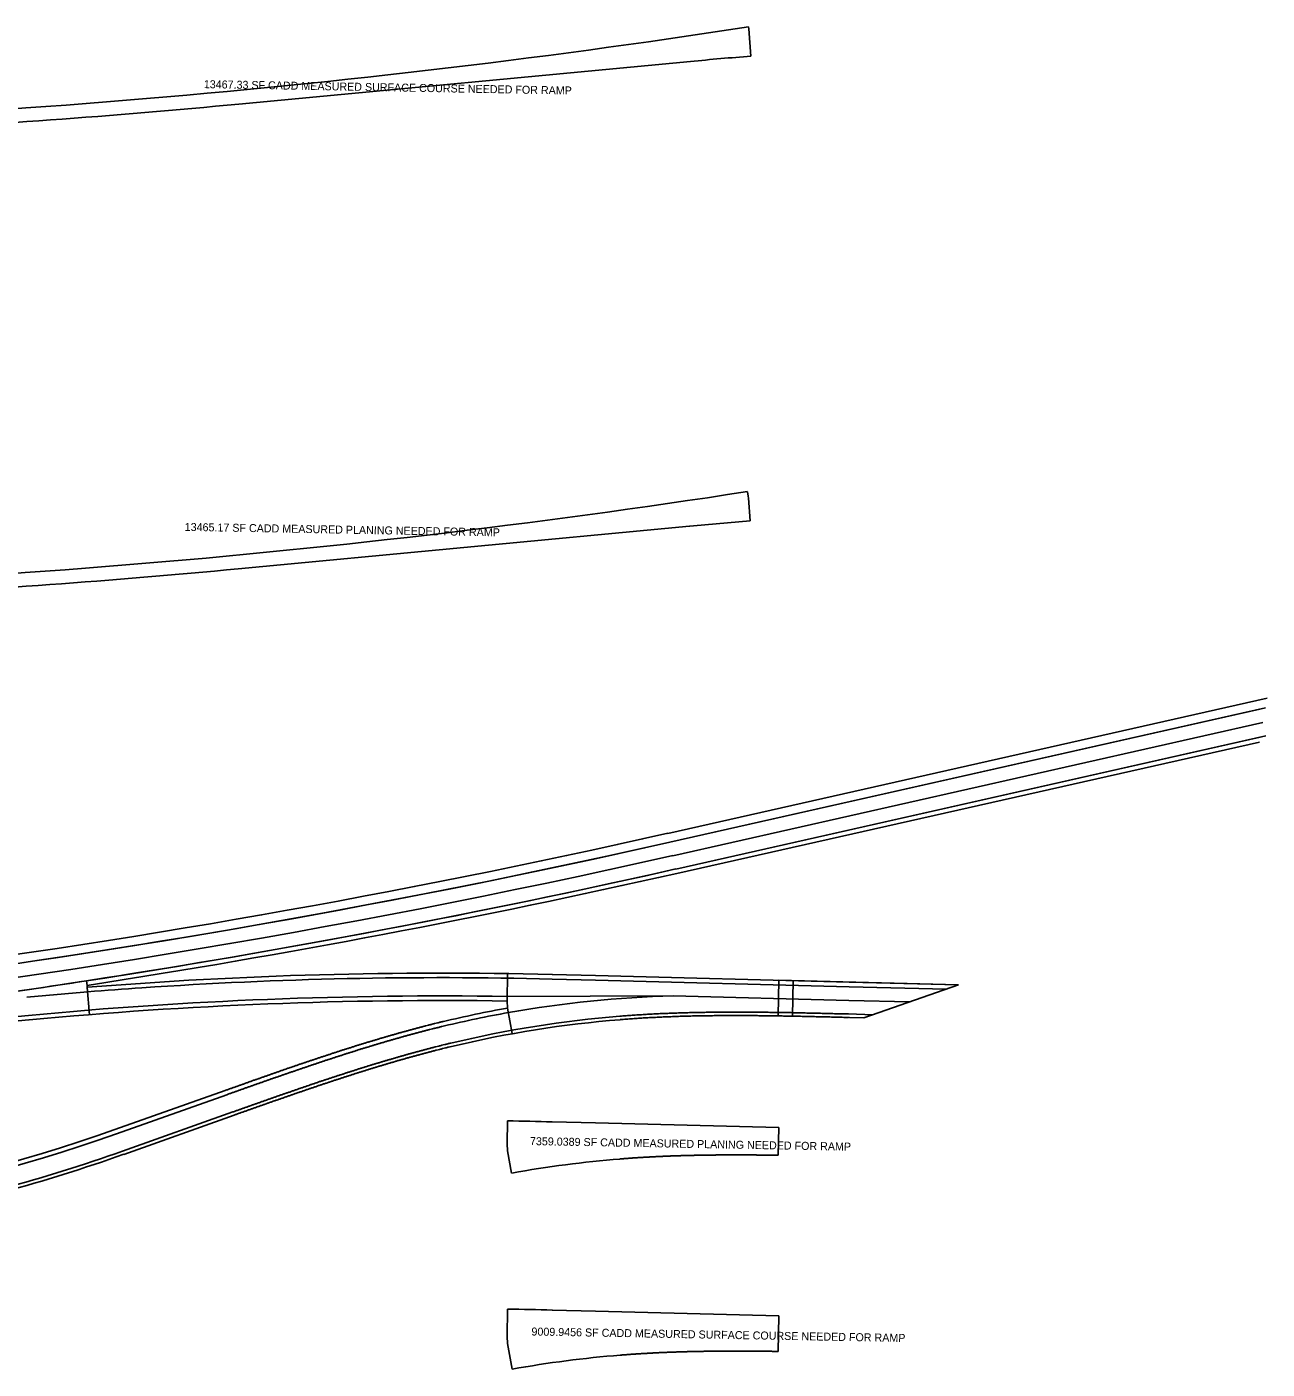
# Model space of a CAD drawing. Extents: x 8527 to 36635, y 12099 to 39012.
# Drawn here: x 10781 to 11866, y 33269 to 34444 of the extents above; entities that cross this region are included whole.
import ezdxf

# ---------------------------------------------------------------- set-up
doc = ezdxf.new("R2010")
doc.units = 0
for name, color, linetype in [('DR_P_Inlet_Protection', 7, 'Continuous'), ('MT_P_Dotted_Line', 7, 'Continuous'), ('MT_P_Traffic_Attenuator', 7, 'Continuous'), ('PV_X_EOP', 7, 'Continuous'), ('SH_Text', 7, 'Continuous')]:
    doc.layers.add(name, color=color, linetype=linetype)

msp = doc.modelspace()

# ---------------------------------------------------------------- linework, layer by layer
at = {"layer": 'DR_P_Inlet_Protection'}
msp.add_line((11345.8, 33718.3), (11861.9, 33834.8), dxfattribs=at)
msp.add_arc((9664.2, 41170.4), 7639.4, 269.175, 282.71667, dxfattribs=at)
at = {"layer": 'MT_P_Dotted_Line'}
for p, q in [((11201, 33595.2), (11346.1, 33595.7)), ((11346.1, 33595.7), (11499.8, 33591.7)), ((11499.8, 33591.7), (11553, 33590.4))]:
    msp.add_line(p, q, dxfattribs=at)
msp.add_arc((11369.8, 32641), 954.9, 91.4213, 100.1187, dxfattribs=at)
at = {"layer": 'MT_P_Traffic_Attenuator'}
for p, q in [((11341.4, 33737.8), (11865.7, 33856.1)), ((11349.4, 33702.7), (11858.9, 33817.7)), ((11201.3, 33615.2), (11200.9, 33591.2)), ((11240.4, 33614.4), (11278.2, 33613.4)), ((11278.2, 33613.4), (11500.2, 33607.7)), ((10833.5, 33604.8), (10833.6, 33603.1)), ((11500.2, 33607.7), (11595.8, 33605.3)), ((11205.3, 33562.6), (11201.3, 33585)), ((10387.7, 33537.1), (10782.6, 33574.6)), ((10857.8, 33478.7), (10954.3, 33512.9)), ((10865.5, 33457), (10962, 33491.2))]:
    msp.add_line(p, q, dxfattribs=at)
for centre, radius, start, end in [((9664.2, 41170.4), 7619.4, 271.81542, 282.71667), ((9664.2, 41170.4), 7655.4, 278.78578, 282.71667), ((11142.7, 29775.9), 3839.7, 88.5417, 94.6175), ((11142.7, 29775.9), 3815.7, 89.126, 95.4147), ((11369.8, 32641), 958.9, 100.1187, 103.5417), ((11375.2, 32625.9), 951.9, 94.5417, 103.5417), ((10380, 34824.8), 1428.4, 268.0856, 289.5417), ((10380, 34824.8), 1451.4, 280.8886, 289.5417)]:
    msp.add_arc(centre, radius, start, end, dxfattribs=at)
for points in [[(11299.8, 33574.9), (11302.5, 33575.1), (11305.2, 33575.3), (11307.9, 33575.5), (11310.5, 33575.7), (11313.2, 33575.9), (11315.9, 33576), (11318.6, 33576.2), (11321.3, 33576.4), (11324, 33576.5), (11326.7, 33576.7), (11329.4, 33576.8), (11332.1, 33576.9), (11334.8, 33577.1), (11337.5, 33577.2), (11340.1, 33577.3), (11342.8, 33577.4), (11345.5, 33577.5), (11348.2, 33577.6), (11350.9, 33577.7), (11353.6, 33577.8), (11356.3, 33577.8), (11359, 33577.9), (11361.7, 33578), (11364.4, 33578.1), (11367.1, 33578.1), (11369.8, 33578.2), (11372.5, 33578.2), (11375.2, 33578.3), (11377.9, 33578.3), (11380.6, 33578.3), (11383.3, 33578.4), (11386, 33578.4), (11388.7, 33578.4), (11391.4, 33578.4), (11394.1, 33578.4), (11396.8, 33578.4), (11399.5, 33578.4), (11402.2, 33578.4), (11404.9, 33578.4), (11407.6, 33578.4), (11410.3, 33578.4), (11413, 33578.4), (11415.7, 33578.4), (11418.4, 33578.4), (11421.1, 33578.3), (11423.8, 33578.3), (11426.5, 33578.3), (11429.2, 33578.3), (11431.9, 33578.2), (11434.6, 33578.2), (11437.3, 33578.1), (11440, 33578.1), (11442.7, 33578), (11445.4, 33578), (11448.1, 33578), (11450.8, 33577.9), (11453.5, 33577.8), (11456.2, 33577.8), (11458.9, 33577.7), (11461.6, 33577.7), (11464.3, 33577.6), (11467, 33577.6), (11469.7, 33577.5), (11472.4, 33577.4), (11475.1, 33577.4), (11477.8, 33577.3), (11480.5, 33577.2), (11483.2, 33577.2), (11485.9, 33577.1), (11488.6, 33577), (11491.3, 33577), (11494, 33576.9), (11496.7, 33576.8), (11499.4, 33576.8)], [(10954.3, 33512.9), (10956.8, 33513.8), (10959.4, 33514.7), (10961.9, 33515.6), (10964.5, 33516.5), (10967, 33517.4), (10969.6, 33518.3), (10972.1, 33519.2), (10974.7, 33520.1), (10977.2, 33521.1), (10979.8, 33522), (10982.3, 33522.8), (10984.9, 33523.7), (10987.4, 33524.6), (10990, 33525.5), (10992.5, 33526.4), (10995.1, 33527.3), (10997.6, 33528.2), (11000.2, 33529.1), (11002.7, 33530), (11005.3, 33530.9), (11007.8, 33531.8), (11010.4, 33532.7), (11013, 33533.5), (11015.5, 33534.4), (11018.1, 33535.3), (11020.6, 33536.2), (11023.2, 33537), (11025.8, 33537.9), (11028.3, 33538.8), (11030.9, 33539.6), (11033.5, 33540.5), (11036, 33541.3), (11038.6, 33542.2), (11041.2, 33543), (11043.8, 33543.9), (11046.3, 33544.7), (11048.9, 33545.6), (11051.5, 33546.4), (11054.1, 33547.3), (11056.6, 33548.1), (11059.2, 33548.9), (11061.8, 33549.7), (11064.4, 33550.5), (11067, 33551.4), (11069.5, 33552.2), (11072.1, 33553), (11074.7, 33553.8), (11077.3, 33554.6), (11079.9, 33555.4), (11082.5, 33556.1), (11085.1, 33556.9), (11087.7, 33557.7), (11090.3, 33558.5), (11092.9, 33559.2), (11095.5, 33560), (11098.1, 33560.8), (11100.7, 33561.5), (11103.3, 33562.2), (11105.9, 33563), (11108.5, 33563.7), (11111.1, 33564.4), (11113.8, 33565.2), (11116.4, 33565.9), (11119, 33566.6), (11121.6, 33567.3), (11124.2, 33568), (11126.9, 33568.7), (11129.5, 33569.4), (11132.1, 33570), (11134.7, 33570.7), (11137.4, 33571.4), (11140, 33572), (11142.6, 33572.7), (11145.3, 33573.3)], [(10962, 33491.2), (10964.5, 33492.2), (10967.1, 33493.1), (10969.6, 33494), (10972.2, 33494.9), (10974.7, 33495.8), (10977.2, 33496.7), (10979.8, 33497.6), (10982.3, 33498.5), (10984.9, 33499.4), (10987.4, 33500.3), (10990, 33501.2), (10992.5, 33502.1), (10995.1, 33503), (10997.6, 33503.9), (11000.2, 33504.7), (11002.7, 33505.6), (11005.3, 33506.5), (11007.8, 33507.4), (11010.4, 33508.3), (11012.9, 33509.2), (11015.5, 33510.1), (11018, 33511), (11020.6, 33511.8), (11023.1, 33512.7), (11025.7, 33513.6), (11028.3, 33514.5), (11030.8, 33515.3), (11033.4, 33516.2), (11035.9, 33517.1), (11038.5, 33517.9), (11041, 33518.8), (11043.6, 33519.6), (11046.2, 33520.5), (11048.7, 33521.3), (11051.3, 33522.2), (11053.9, 33523), (11056.4, 33523.8), (11059, 33524.7), (11061.6, 33525.5), (11064.1, 33526.3), (11066.7, 33527.2), (11069.3, 33528), (11071.8, 33528.8), (11074.4, 33529.6), (11077, 33530.4), (11079.6, 33531.2), (11082.1, 33532), (11084.7, 33532.8), (11087.3, 33533.6), (11089.9, 33534.4), (11092.5, 33535.1), (11095, 33535.9), (11097.6, 33536.7), (11100.2, 33537.4), (11102.8, 33538.2), (11105.4, 33539), (11108, 33539.7), (11110.6, 33540.4), (11113.2, 33541.2), (11115.8, 33541.9), (11118.4, 33542.6), (11121, 33543.3), (11123.6, 33544), (11126.2, 33544.7), (11128.8, 33545.4), (11131.4, 33546.1), (11134, 33546.8), (11136.6, 33547.5), (11139.2, 33548.2), (11141.8, 33548.8), (11144.4, 33549.5), (11147, 33550.1), (11149.7, 33550.8), (11152.3, 33551.4)]]:
    msp.add_spline(points, degree=3, dxfattribs=at)
at = {"layer": 'PV_X_EOP'}
msp.add_arc((11142.7, 29775.9), 3835.7, 94.6175, 95.4147, dxfattribs=at)
at = {"layer": 'SH_Text'}
for p, q in [((11412, 34443.5), (11412.2, 34441.9)), ((11412.2, 34441.9), (11414.1, 34418)), ((11361.2, 34413.3), (10966.3, 34375.9)), ((11411.1, 34036.8), (11411.7, 34032.9)), ((11411.7, 34032.9), (11411.9, 34031.2)), ((11411.9, 34031.2), (11413.5, 34011.3)), ((11360.5, 34006.7), (10965.6, 33969.2)), ((11343.2, 33730), (11864.2, 33847.6)), ((11343.2, 33730), (11859.3, 33846.5)), ((11348.5, 33706.6), (11864.6, 33823.1)), ((11348.5, 33706.6), (11859.7, 33822)), ((10832.8, 33608.7), (10833.5, 33604.8)), ((10835.5, 33579.2), (10833.6, 33603.1)), ((11240.3, 33610.4), (11278.1, 33609.4)), ((11278.1, 33609.4), (11500.1, 33603.7)), ((11438, 33578.1), (11438.5, 33609.3)), ((11438.5, 33609.3), (11438, 33578.1)), ((11438.5, 33609.3), (11595.8, 33605.3)), ((11451, 33609.1), (11450.5, 33577.9)), ((11500.1, 33603.7), (11585.1, 33601.6)), ((11595.8, 33605.3), (11512.9, 33576.4)), ((11201.3, 33585), (11200.9, 33591.2)), ((10387.3, 33541.1), (10782.3, 33578.6)), ((11512.9, 33576.4), (11438, 33578.1)), ((11499.4, 33579.8), (11499.5, 33579.8)), ((11499.5, 33579.8), (11520.9, 33579.2)), ((10859.2, 33474.9), (10955.6, 33509.2)), ((10864.5, 33459.8), (10961, 33494.1)), ((11201.2, 33486.2), (11200.9, 33466.2)), ((11278.1, 33484.5), (11240.3, 33485.4)), ((11438.5, 33480.4), (11278.1, 33484.5)), ((11438.1, 33456.2), (11438.5, 33480.4)), ((11200.9, 33466.2), (11201.3, 33460.1)), ((11201.3, 33460.1), (11204.8, 33440.6)), ((11201.3, 33321.6), (11200.9, 33297.6)), ((11278.2, 33319.8), (11240.4, 33320.8)), ((11438.5, 33315.8), (11278.2, 33319.8)), ((11438, 33284.6), (11438.5, 33315.8)), ((11200.9, 33297.6), (11201.3, 33291.5)), ((11201.3, 33291.5), (11205.3, 33269))]:
    msp.add_line(p, q, dxfattribs=at)
for centre, radius, start, end in [((10242.8, 42009.1), 7655.4, 270.31719, 278.78578), ((11721.3, 30614.6), 3815.7, 94.6175, 95.4147), ((10242.8, 42009.1), 7667.4, 272.94219, 275.4147), ((10242.4, 41598.5), 7651.4, 270.3177, 278.78578), ((11721, 30204), 3819.7, 94.6175, 95.4147), ((10242.4, 41598.5), 7663.4, 272.9427, 275.4147), ((9664.2, 41170.4), 7627.4, 269.175, 282.71667), ((9664.2, 41170.4), 7627.4, 271.80788, 282.71667), ((9664.2, 41170.4), 7651.4, 269.175, 282.71667), ((9664.2, 41170.4), 7651.4, 278.78578, 282.71667), ((9664.2, 41170.4), 7651.4, 277.26554, 278.78578), ((11142.7, 29775.9), 3835.7, 93.9053, 94.6175), ((11142.7, 29775.9), 3835.7, 88.5417, 93.9053), ((11142.7, 29775.9), 3819.7, 89.126, 95.4147), ((11369.8, 32641), 954.9, 100.1187, 103.5417), ((11375.2, 32625.9), 954.9, 94.5417, 103.5417), ((11142.7, 29651), 3835.7, 88.5417, 89.126), ((10380, 34824.8), 1432.4, 268.0856, 289.5417), ((10380, 34824.8), 1448.4, 280.8886, 289.5417), ((11375.2, 32501), 954.9, 94.5417, 100.2758), ((11142.7, 29482.3), 3839.7, 88.5417, 89.126), ((11375.2, 32332.4), 951.9, 94.5417, 100.2763)]:
    msp.add_arc(centre, radius, start, end, dxfattribs=at)
for points in [[(11299.6, 33577.9), (11302.2, 33578.1), (11304.9, 33578.3), (11307.6, 33578.5), (11310.3, 33578.7), (11313, 33578.9), (11315.7, 33579), (11318.4, 33579.2), (11321.1, 33579.4), (11323.8, 33579.5), (11326.5, 33579.7), (11329.2, 33579.8), (11331.9, 33579.9), (11334.6, 33580.1), (11337.3, 33580.2), (11340, 33580.3), (11342.7, 33580.4), (11345.4, 33580.5), (11348.1, 33580.6), (11350.8, 33580.7), (11353.5, 33580.8), (11356.2, 33580.8), (11358.9, 33580.9), (11361.6, 33581), (11364.3, 33581), (11367, 33581.1), (11369.7, 33581.2), (11372.4, 33581.2), (11375.1, 33581.3), (11377.8, 33581.3), (11380.5, 33581.3), (11383.2, 33581.4), (11386, 33581.4), (11388.7, 33581.4), (11391.4, 33581.4), (11394.1, 33581.4), (11396.8, 33581.4), (11399.5, 33581.4), (11402.2, 33581.4), (11404.9, 33581.4), (11407.6, 33581.4), (11410.3, 33581.4), (11413, 33581.4), (11415.7, 33581.4), (11418.4, 33581.4), (11421.1, 33581.3), (11423.8, 33581.3), (11426.5, 33581.3), (11429.2, 33581.3), (11431.9, 33581.2), (11434.6, 33581.2), (11437.3, 33581.1), (11440, 33581.1), (11442.7, 33581), (11445.4, 33581), (11448.1, 33581), (11450.8, 33580.9), (11453.5, 33580.8), (11456.2, 33580.8), (11458.9, 33580.7), (11461.6, 33580.7), (11464.3, 33580.6), (11467, 33580.6), (11469.7, 33580.5), (11472.4, 33580.4), (11475.1, 33580.4), (11477.8, 33580.3), (11480.5, 33580.2), (11483.2, 33580.2), (11485.9, 33580.1), (11488.6, 33580), (11491.3, 33580), (11494, 33579.9), (11496.7, 33579.8), (11499.4, 33579.8)], [(10955.6, 33509.2), (10958.2, 33510.1), (10960.7, 33511), (10963.3, 33511.9), (10965.8, 33512.8), (10968.3, 33513.7), (10970.9, 33514.6), (10973.4, 33515.5), (10976, 33516.4), (10978.5, 33517.3), (10981.1, 33518.2), (10983.6, 33519.1), (10986.2, 33520), (10988.7, 33520.9), (10991.3, 33521.8), (10993.8, 33522.7), (10996.4, 33523.6), (10998.9, 33524.4), (11001.5, 33525.3), (11004, 33526.2), (11006.6, 33527.1), (11009.2, 33528), (11011.7, 33528.9), (11014.3, 33529.7), (11016.8, 33530.6), (11019.4, 33531.5), (11021.9, 33532.4), (11024.5, 33533.2), (11027.1, 33534.1), (11029.6, 33535), (11032.2, 33535.8), (11034.7, 33536.7), (11037.3, 33537.5), (11039.9, 33538.4), (11042.4, 33539.3), (11045, 33540.1), (11047.6, 33540.9), (11050.1, 33541.8), (11052.7, 33542.6), (11055.3, 33543.4), (11057.9, 33544.3), (11060.4, 33545.1), (11063, 33545.9), (11065.6, 33546.7), (11068.2, 33547.5), (11070.7, 33548.4), (11073.3, 33549.2), (11075.9, 33550), (11078.5, 33550.7), (11081.1, 33551.5), (11083.7, 33552.3), (11086.2, 33553.1), (11088.8, 33553.9), (11091.4, 33554.6), (11094, 33555.4), (11096.6, 33556.2), (11099.2, 33556.9), (11101.8, 33557.7), (11104.4, 33558.4), (11107, 33559.1), (11109.6, 33559.9), (11112.2, 33560.6), (11114.8, 33561.3), (11117.4, 33562), (11120, 33562.7), (11122.6, 33563.4), (11125.3, 33564.1), (11127.9, 33564.8), (11130.5, 33565.5), (11133.1, 33566.2), (11135.7, 33566.8), (11138.3, 33567.5), (11141, 33568.1), (11143.6, 33568.8), (11146.2, 33569.4)], [(10961, 33494.1), (10963.5, 33495), (10966.1, 33495.9), (10968.6, 33496.8), (10971.2, 33497.7), (10973.7, 33498.6), (10976.2, 33499.5), (10978.8, 33500.4), (10981.3, 33501.3), (10983.9, 33502.2), (10986.4, 33503.1), (10989, 33504), (10991.5, 33504.9), (10994.1, 33505.8), (10996.6, 33506.7), (10999.2, 33507.6), (11001.7, 33508.5), (11004.3, 33509.4), (11006.8, 33510.3), (11009.4, 33511.1), (11012, 33512), (11014.5, 33512.9), (11017.1, 33513.8), (11019.6, 33514.7), (11022.2, 33515.5), (11024.7, 33516.4), (11027.3, 33517.3), (11029.8, 33518.2), (11032.4, 33519), (11035, 33519.9), (11037.5, 33520.8), (11040.1, 33521.6), (11042.7, 33522.5), (11045.2, 33523.3), (11047.8, 33524.2), (11050.4, 33525), (11052.9, 33525.9), (11055.5, 33526.7), (11058.1, 33527.5), (11060.6, 33528.4), (11063.2, 33529.2), (11065.8, 33530), (11068.4, 33530.8), (11070.9, 33531.7), (11073.5, 33532.5), (11076.1, 33533.3), (11078.7, 33534.1), (11081.3, 33534.9), (11083.8, 33535.7), (11086.4, 33536.5), (11089, 33537.2), (11091.6, 33538), (11094.2, 33538.8), (11096.8, 33539.6), (11099.4, 33540.3), (11102, 33541.1), (11104.6, 33541.8), (11107.2, 33542.6), (11109.8, 33543.3), (11112.4, 33544.1), (11115, 33544.8), (11117.6, 33545.5), (11120.2, 33546.2), (11122.8, 33546.9), (11125.4, 33547.6), (11128, 33548.3), (11130.6, 33549), (11133.2, 33549.7), (11135.8, 33550.4), (11138.5, 33551.1), (11141.1, 33551.7), (11143.7, 33552.4), (11146.3, 33553), (11148.9, 33553.7), (11151.6, 33554.3)]]:
    msp.add_spline(points, degree=3, dxfattribs=at)
for points in [[(11299.6, 33453), (11300.5, 33453), (11301.4, 33453.1), (11302.2, 33453.2), (11303.1, 33453.2), (11304, 33453.3), (11304.9, 33453.4), (11305.8, 33453.4), (11306.7, 33453.5), (11307.6, 33453.6), (11308.5, 33453.6), (11309.4, 33453.7), (11310.3, 33453.8), (11311.2, 33453.8), (11312.1, 33453.9), (11313, 33453.9), (11313.9, 33454), (11314.8, 33454.1), (11315.7, 33454.1), (11316.6, 33454.2), (11317.5, 33454.2), (11318.4, 33454.3), (11319.3, 33454.3), (11320.2, 33454.4), (11321.1, 33454.4), (11322, 33454.5), (11322.9, 33454.5), (11323.8, 33454.6), (11324.7, 33454.6), (11325.6, 33454.7), (11326.5, 33454.7), (11327.4, 33454.8), (11328.3, 33454.8), (11329.2, 33454.9), (11330.1, 33454.9), (11331, 33455), (11331.9, 33455), (11332.8, 33455.1), (11333.7, 33455.1), (11334.6, 33455.1), (11335.5, 33455.2), (11336.4, 33455.2), (11337.3, 33455.3), (11338.2, 33455.3), (11339.1, 33455.3), (11340, 33455.4), (11340.9, 33455.4), (11341.8, 33455.4), (11342.7, 33455.5), (11343.6, 33455.5), (11344.5, 33455.6), (11345.4, 33455.6), (11346.3, 33455.6), (11347.2, 33455.7), (11348.1, 33455.7), (11349, 33455.7), (11349.9, 33455.7), (11350.8, 33455.8), (11351.7, 33455.8), (11352.6, 33455.8), (11353.5, 33455.9), (11354.4, 33455.9), (11355.3, 33455.9), (11356.2, 33455.9), (11357.1, 33456), (11358, 33456), (11358.9, 33456), (11359.8, 33456), (11360.7, 33456.1), (11361.6, 33456.1), (11362.5, 33456.1), (11363.4, 33456.1), (11364.3, 33456.1), (11365.2, 33456.2), (11366.1, 33456.2), (11367, 33456.2), (11367.9, 33456.2), (11368.8, 33456.2), (11369.7, 33456.3), (11370.6, 33456.3), (11371.5, 33456.3), (11372.4, 33456.3), (11373.3, 33456.3), (11374.2, 33456.3), (11375.1, 33456.3), (11376, 33456.4), (11376.9, 33456.4), (11377.8, 33456.4), (11378.7, 33456.4), (11379.6, 33456.4), (11380.5, 33456.4), (11381.4, 33456.4), (11382.3, 33456.4), (11383.2, 33456.4), (11384.1, 33456.5), (11385.1, 33456.5), (11386, 33456.5), (11386.9, 33456.5), (11387.8, 33456.5), (11388.7, 33456.5), (11389.6, 33456.5), (11390.5, 33456.5), (11391.4, 33456.5), (11392.3, 33456.5), (11393.2, 33456.5), (11394.1, 33456.5), (11395, 33456.5), (11395.9, 33456.5), (11396.8, 33456.5), (11397.7, 33456.5), (11398.6, 33456.5), (11399.5, 33456.5), (11400.4, 33456.5), (11401.3, 33456.5), (11402.2, 33456.5), (11403.1, 33456.5), (11404, 33456.5), (11404.9, 33456.5), (11405.8, 33456.5), (11406.7, 33456.5), (11407.6, 33456.5), (11408.5, 33456.5), (11409.4, 33456.5), (11410.3, 33456.5), (11411.2, 33456.5), (11412.1, 33456.5), (11413, 33456.5), (11413.9, 33456.5), (11414.8, 33456.5), (11415.7, 33456.5), (11416.6, 33456.5), (11417.5, 33456.5), (11418.4, 33456.5), (11419.3, 33456.4), (11420.2, 33456.4), (11421.1, 33456.4), (11422, 33456.4), (11422.9, 33456.4), (11423.8, 33456.4), (11424.7, 33456.4), (11425.6, 33456.4), (11426.5, 33456.4), (11427.4, 33456.4), (11428.3, 33456.4), (11429.2, 33456.3), (11430.1, 33456.3), (11431, 33456.3), (11431.9, 33456.3), (11432.8, 33456.3), (11433.7, 33456.3), (11434.6, 33456.3), (11435.5, 33456.3), (11436.4, 33456.2), (11437.3, 33456.2), (11437.6, 33456.2), (11437.8, 33456.2), (11438.1, 33456.2)], [(11299.8, 33281.3), (11300.7, 33281.4), (11301.6, 33281.5), (11302.5, 33281.5), (11303.4, 33281.6), (11304.3, 33281.7), (11305.2, 33281.7), (11306.1, 33281.8), (11307, 33281.9), (11307.9, 33281.9), (11308.7, 33282), (11309.6, 33282.1), (11310.5, 33282.1), (11311.4, 33282.2), (11312.3, 33282.2), (11313.2, 33282.3), (11314.1, 33282.4), (11315, 33282.4), (11315.9, 33282.5), (11316.8, 33282.5), (11317.7, 33282.6), (11318.6, 33282.6), (11319.5, 33282.7), (11320.4, 33282.7), (11321.3, 33282.8), (11322.2, 33282.8), (11323.1, 33282.9), (11324, 33282.9), (11324.9, 33283), (11325.8, 33283), (11326.7, 33283.1), (11327.6, 33283.1), (11328.5, 33283.2), (11329.4, 33283.2), (11330.3, 33283.3), (11331.2, 33283.3), (11332.1, 33283.4), (11333, 33283.4), (11333.9, 33283.5), (11334.8, 33283.5), (11335.7, 33283.5), (11336.6, 33283.6), (11337.5, 33283.6), (11338.3, 33283.7), (11339.2, 33283.7), (11340.1, 33283.7), (11341, 33283.8), (11341.9, 33283.8), (11342.8, 33283.8), (11343.7, 33283.9), (11344.6, 33283.9), (11345.5, 33283.9), (11346.4, 33284), (11347.3, 33284), (11348.2, 33284), (11349.1, 33284.1), (11350, 33284.1), (11350.9, 33284.1), (11351.8, 33284.2), (11352.7, 33284.2), (11353.6, 33284.2), (11354.5, 33284.2), (11355.4, 33284.3), (11356.3, 33284.3), (11357.2, 33284.3), (11358.1, 33284.3), (11359, 33284.4), (11359.9, 33284.4), (11360.8, 33284.4), (11361.7, 33284.4), (11362.6, 33284.4), (11363.5, 33284.5), (11364.4, 33284.5), (11365.3, 33284.5), (11366.2, 33284.5), (11367.1, 33284.5), (11368, 33284.6), (11368.9, 33284.6), (11369.8, 33284.6), (11370.7, 33284.6), (11371.6, 33284.6), (11372.5, 33284.6), (11373.4, 33284.7), (11374.3, 33284.7), (11375.2, 33284.7), (11376.1, 33284.7), (11377, 33284.7), (11377.9, 33284.7), (11378.8, 33284.7), (11379.7, 33284.8), (11380.6, 33284.8), (11381.5, 33284.8), (11382.4, 33284.8), (11383.3, 33284.8), (11384.2, 33284.8), (11385.1, 33284.8), (11386, 33284.8), (11386.9, 33284.8), (11387.8, 33284.8), (11388.7, 33284.8), (11389.6, 33284.8), (11390.5, 33284.8), (11391.4, 33284.9), (11392.3, 33284.9), (11393.2, 33284.9), (11394.1, 33284.9), (11395, 33284.9), (11395.9, 33284.9), (11396.8, 33284.9), (11397.7, 33284.9), (11398.6, 33284.9), (11399.5, 33284.9), (11400.4, 33284.9), (11401.3, 33284.9), (11402.2, 33284.9), (11403.1, 33284.9), (11404, 33284.9), (11404.9, 33284.9), (11405.8, 33284.9), (11406.7, 33284.9), (11407.6, 33284.9), (11408.5, 33284.9), (11409.4, 33284.9), (11410.3, 33284.9), (11411.2, 33284.9), (11412.1, 33284.8), (11413, 33284.8), (11413.9, 33284.8), (11414.8, 33284.8), (11415.7, 33284.8), (11416.6, 33284.8), (11417.5, 33284.8), (11418.4, 33284.8), (11419.3, 33284.8), (11420.2, 33284.8), (11421.1, 33284.8), (11422, 33284.8), (11422.9, 33284.8), (11423.8, 33284.8), (11424.7, 33284.7), (11425.6, 33284.7), (11426.5, 33284.7), (11427.4, 33284.7), (11428.3, 33284.7), (11429.2, 33284.7), (11430.1, 33284.7), (11431, 33284.7), (11431.9, 33284.7), (11432.8, 33284.6), (11433.7, 33284.6), (11434.6, 33284.6), (11435.5, 33284.6), (11436.4, 33284.6), (11437.3, 33284.6), (11437.5, 33284.6), (11437.8, 33284.6), (11438, 33284.6)]]:
    msp.add_open_spline(points, degree=3, dxfattribs=at)

# ---------------------------------------------------------------- texts
for s, p in [('13467.33 SF CADD MEASURED SURFACE COURSE NEEDED FOR RAMP', (10935.5, 34389.9)), ('13465.17 SF CADD MEASURED PLANING NEEDED FOR RAMP', (10918.8, 34002.5)), ('7359.0389 SF CADD MEASURED PLANING NEEDED FOR RAMP', (11220.8, 33465.1)), ('9009.9456 SF CADD MEASURED SURFACE COURSE NEEDED FOR RAMP', (11222.1, 33298.5))]:
    msp.add_text(s, height=7, rotation=359, dxfattribs=at).set_placement(p)

doc.saveas('drawing.dxf')
